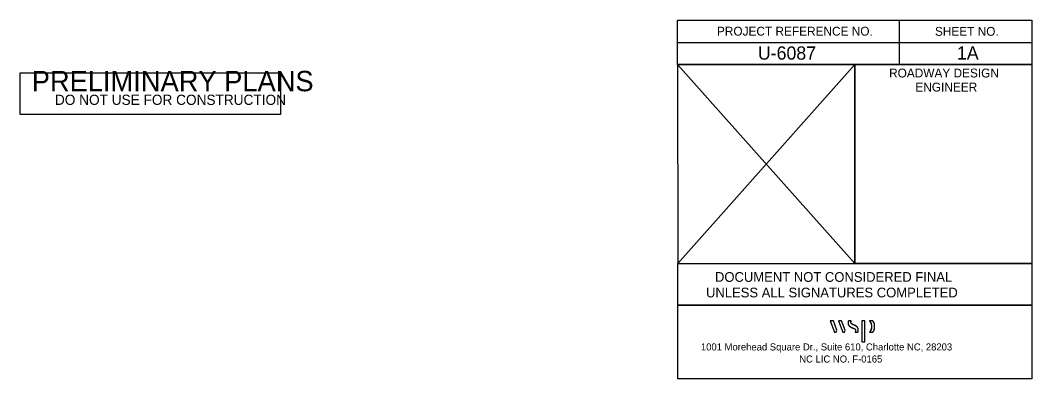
# Model space of a CAD drawing. Extents: x 1844369 to 1844800, y 671424 to 671721.
# Drawn here: x 1844582.98 to 1844631.58, y 671592.91 to 671610.14 of the extents above; entities that cross this region are included whole.
import ezdxf

# ---------------------------------------------------------------- set-up
doc = ezdxf.new("R2010")
doc.units = 0
for name, color, linetype in [('Default', 7, 'Continuous'), ('Sheet Data Field CELL', 7, 'Continuous'), ('Sheet Plan CELL', 7, 'Continuous'), ('Sheet Sticker Exception Certification CELL', 7, 'Continuous'), ('Sheet Sticker Preliminary CELL', 7, 'Continuous'), ('Sheet Title CELL', 7, 'Continuous')]:
    doc.layers.add(name, color=color, linetype=linetype)

msp = doc.modelspace()

# ---------------------------------------------------------------- linework, layer by layer
at = {"layer": 'Default'}
for p, q in [((1844622.047, 671595.689), (1844621.9, 671595.689)), ((1844621.9, 671595.689), (1844622.102, 671595.143)), ((1844622.214, 671595.236), (1844622.047, 671595.689)), ((1844622.441, 671595.689), (1844622.294, 671595.689)), ((1844622.294, 671595.689), (1844622.495, 671595.143)), ((1844622.608, 671595.236), (1844622.441, 671595.689)), ((1844623.562, 671595.689), (1844623.421, 671595.689)), ((1844623.421, 671595.689), (1844623.421, 671595.248)), ((1844623.562, 671595.648), (1844623.562, 671595.689)), ((1844623.562, 671595.632), (1844623.562, 671595.648)), ((1844623.562, 671595.604), (1844623.562, 671595.632)), ((1844623.562, 671595.248), (1844623.562, 671595.604)), ((1844622.102, 671595.143), (1844622.18, 671595.143)), ((1844622.18, 671595.143), (1844622.214, 671595.236)), ((1844622.495, 671595.143), (1844622.573, 671595.143)), ((1844622.573, 671595.143), (1844622.608, 671595.236)), ((1844623.421, 671595.248), (1844623.421, 671594.68)), ((1844623.562, 671595.207), (1844623.562, 671595.248)), ((1844623.562, 671595.194), (1844623.562, 671595.207)), ((1844623.562, 671594.68), (1844623.562, 671595.194)), ((1844623.421, 671594.68), (1844623.562, 671594.68))]:
    msp.add_line(p, q, dxfattribs=at)
for points in [[(1844622.047, 671595.689), (1844621.9, 671595.689), (1844622.102, 671595.143), (1844622.18, 671595.143), (1844622.214, 671595.236), (1844622.047, 671595.689)], [(1844622.441, 671595.689), (1844622.294, 671595.689), (1844622.495, 671595.143), (1844622.573, 671595.143), (1844622.608, 671595.236), (1844622.441, 671595.689)], [(1844623.562, 671594.68), (1844623.562, 671595.194), (1844623.562, 671595.207), (1844623.562, 671595.248), (1844623.562, 671595.604), (1844623.562, 671595.632), (1844623.562, 671595.648), (1844623.562, 671595.689), (1844623.421, 671595.689), (1844623.421, 671595.248), (1844623.421, 671594.68), (1844623.562, 671594.68)]]:
    msp.add_lwpolyline(points, dxfattribs=at)
for points, degree in [([(1844622.757, 671595.608), (1844622.759, 671595.636), (1844622.764, 671595.664), (1844622.776, 671595.689), (1844622.776, 671595.689), (1844622.904, 671595.689), (1844622.904, 671595.689), (1844622.893, 671595.67), (1844622.883, 671595.635), (1844622.895, 671595.599), (1844622.905, 671595.568), (1844622.927, 671595.546), (1844622.955, 671595.528), (1844622.987, 671595.507), (1844623.026, 671595.495), (1844623.061, 671595.479), (1844623.098, 671595.462), (1844623.134, 671595.444), (1844623.164, 671595.417), (1844623.209, 671595.378), (1844623.236, 671595.332), (1844623.241, 671595.273), (1844623.241, 671595.266), (1844623.242, 671595.258), (1844623.242, 671595.251), (1844623.242, 671595.214), (1844623.236, 671595.177), (1844623.219, 671595.143), (1844623.219, 671595.143), (1844623.087, 671595.143), (1844623.087, 671595.143), (1844623.1, 671595.165), (1844623.11, 671595.195), (1844623.109, 671595.223), (1844623.104, 671595.292), (1844623.02, 671595.33), (1844622.95, 671595.361), (1844622.939, 671595.366), (1844622.928, 671595.37), (1844622.918, 671595.375), (1844622.887, 671595.389), (1844622.857, 671595.406), (1844622.831, 671595.428), (1844622.803, 671595.451), (1844622.783, 671595.473), (1844622.77, 671595.507), (1844622.759, 671595.536), (1844622.755, 671595.567), (1844622.756, 671595.598), (1844622.756, 671595.602), (1844622.756, 671595.605), (1844622.757, 671595.608)], 2), ([(1844622.757, 671595.608), (1844622.759, 671595.636), (1844622.764, 671595.664), (1844622.776, 671595.689), (1844622.776, 671595.689), (1844622.904, 671595.689), (1844622.904, 671595.689), (1844622.893, 671595.67), (1844622.883, 671595.635), (1844622.895, 671595.599), (1844622.905, 671595.568), (1844622.927, 671595.546), (1844622.955, 671595.528), (1844622.987, 671595.507), (1844623.026, 671595.495), (1844623.061, 671595.479), (1844623.098, 671595.462), (1844623.134, 671595.444), (1844623.164, 671595.417), (1844623.209, 671595.378), (1844623.236, 671595.332), (1844623.241, 671595.273), (1844623.241, 671595.266), (1844623.242, 671595.258), (1844623.242, 671595.251), (1844623.242, 671595.214), (1844623.236, 671595.177), (1844623.219, 671595.143), (1844623.219, 671595.143), (1844623.087, 671595.143), (1844623.087, 671595.143), (1844623.1, 671595.165), (1844623.11, 671595.195), (1844623.109, 671595.223), (1844623.104, 671595.292), (1844623.02, 671595.33), (1844622.95, 671595.361), (1844622.939, 671595.366), (1844622.928, 671595.37), (1844622.918, 671595.375), (1844622.887, 671595.389), (1844622.857, 671595.406), (1844622.831, 671595.428), (1844622.803, 671595.451), (1844622.783, 671595.473), (1844622.77, 671595.507), (1844622.759, 671595.536), (1844622.755, 671595.567), (1844622.756, 671595.598), (1844622.756, 671595.602), (1844622.756, 671595.605), (1844622.757, 671595.608)], 3), ([(1844623.875, 671595.417), (1844623.875, 671595.531), (1844623.834, 671595.627), (1844623.779, 671595.689), (1844623.779, 671595.689), (1844623.938, 671595.689), (1844623.938, 671595.689), (1844623.99, 671595.626), (1844624.022, 671595.517), (1844624.022, 671595.417), (1844624.022, 671595.417), (1844624.022, 671595.416), (1844624.022, 671595.416), (1844624.022, 671595.315), (1844623.99, 671595.207), (1844623.938, 671595.143), (1844623.938, 671595.143), (1844623.779, 671595.143), (1844623.779, 671595.143), (1844623.833, 671595.206), (1844623.875, 671595.302), (1844623.875, 671595.416), (1844623.875, 671595.416), (1844623.875, 671595.417), (1844623.875, 671595.417)], 2), ([(1844623.875, 671595.417), (1844623.875, 671595.531), (1844623.834, 671595.627), (1844623.779, 671595.689), (1844623.779, 671595.689), (1844623.938, 671595.689), (1844623.938, 671595.689), (1844623.99, 671595.626), (1844624.022, 671595.517), (1844624.022, 671595.417), (1844624.022, 671595.417), (1844624.022, 671595.416), (1844624.022, 671595.416), (1844624.022, 671595.315), (1844623.99, 671595.207), (1844623.938, 671595.143), (1844623.938, 671595.143), (1844623.779, 671595.143), (1844623.779, 671595.143), (1844623.833, 671595.206), (1844623.875, 671595.302), (1844623.875, 671595.416), (1844623.875, 671595.416), (1844623.875, 671595.417), (1844623.875, 671595.417)], 3)]:
    msp.add_open_spline(points, degree=degree, dxfattribs=at)
at = {"layer": 'Sheet Plan CELL'}
for p, q in [((1844625.199, 671610.138), (1844625.199, 671608.012)), ((1844614.566, 671609.075), (1844631.577, 671609.075)), ((1844614.566, 671608.012), (1844614.567, 671598.447)), ((1844614.566, 671608.012), (1844631.577, 671608.012)), ((1844614.566, 671608.012), (1844631.577, 671608.012)), ((1844623.073, 671598.446), (1844614.566, 671608.012)), ((1844623.073, 671608.012), (1844614.567, 671598.447)), ((1844623.073, 671608.012), (1844623.073, 671598.45))]:
    msp.add_line(p, q, dxfattribs=at)
for points in [[(1844614.566, 671610.142), (1844631.577, 671610.142), (1844631.577, 671608.012), (1844614.566, 671608.012)], [(1844623.073, 671608.012), (1844631.577, 671608.012), (1844631.577, 671598.446), (1844623.073, 671598.446)], [(1844614.567, 671596.449), (1844631.577, 671596.449), (1844631.577, 671592.907), (1844614.567, 671592.907)]]:
    msp.add_lwpolyline(points, close=True, dxfattribs=at)
at = {"layer": 'Sheet Sticker Exception Certification CELL'}
for p, q in [((1844614.567, 671596.449), (1844614.567, 671598.447)), ((1844614.567, 671598.447), (1844631.577, 671598.447)), ((1844631.577, 671598.446), (1844631.577, 671596.448)), ((1844631.577, 671596.449), (1844614.567, 671596.449))]:
    msp.add_line(p, q, dxfattribs=at)
at = {"layer": 'Sheet Sticker Preliminary CELL'}
msp.add_lwpolyline([(1844582.985, 671605.608), (1844582.985, 671607.607), (1844595.485, 671607.607), (1844595.485, 671605.608)], close=True, dxfattribs=at)

# ---------------------------------------------------------------- texts
at = {"layer": 'Sheet Data Field CELL'}
for s, p in [('U-6087', (1844618.419, 671608.246)), ('1A', (1844627.981, 671608.25))]:
    msp.add_text(s, height=0.6377, dxfattribs=at).set_placement(p)
at = {"layer": 'Sheet Plan CELL'}
for s, height, p in [('PROJECT REFERENCE NO.', 0.42517, (1844616.454, 671609.402)), ('SHEET NO.', 0.4252, (1844626.925, 671609.394)), ('ROADWAY DESIGN', 0.42517, (1844624.723, 671607.391)), ('ENGINEER', 0.4252, (1844625.986, 671606.715))]:
    msp.add_text(s, height=height, dxfattribs=at).set_placement(p)
at = {"layer": 'Sheet Sticker Exception Certification CELL'}
for s, p in [('DOCUMENT NOT CONSIDERED FINAL', (1844616.359, 671597.567)), ('UNLESS ALL SIGNATURES COMPLETED', (1844615.927, 671596.819))]:
    msp.add_text(s, height=0.46768, dxfattribs=at).set_placement(p)
at = {"layer": 'Sheet Sticker Preliminary CELL'}
for s, height, p in [('PRELIMINARY PLANS', 0.97958, (1844583.538, 671606.727)), ('DO NOT USE FOR CONSTRUCTION', 0.48979, (1844584.652, 671606.072))]:
    msp.add_text(s, height=height, dxfattribs=at).set_placement(p)
at = {"layer": 'Sheet Title CELL'}
for s, p in [('1001 Morehead Square Dr., Suite 610, Charlotte NC, 28203', (1844615.684, 671594.268)), ('NC LIC NO. F-0165', (1844620.408, 671593.687))]:
    msp.add_text(s, height=0.33966, rotation=360, dxfattribs=at).set_placement(p)

doc.saveas('drawing.dxf')
